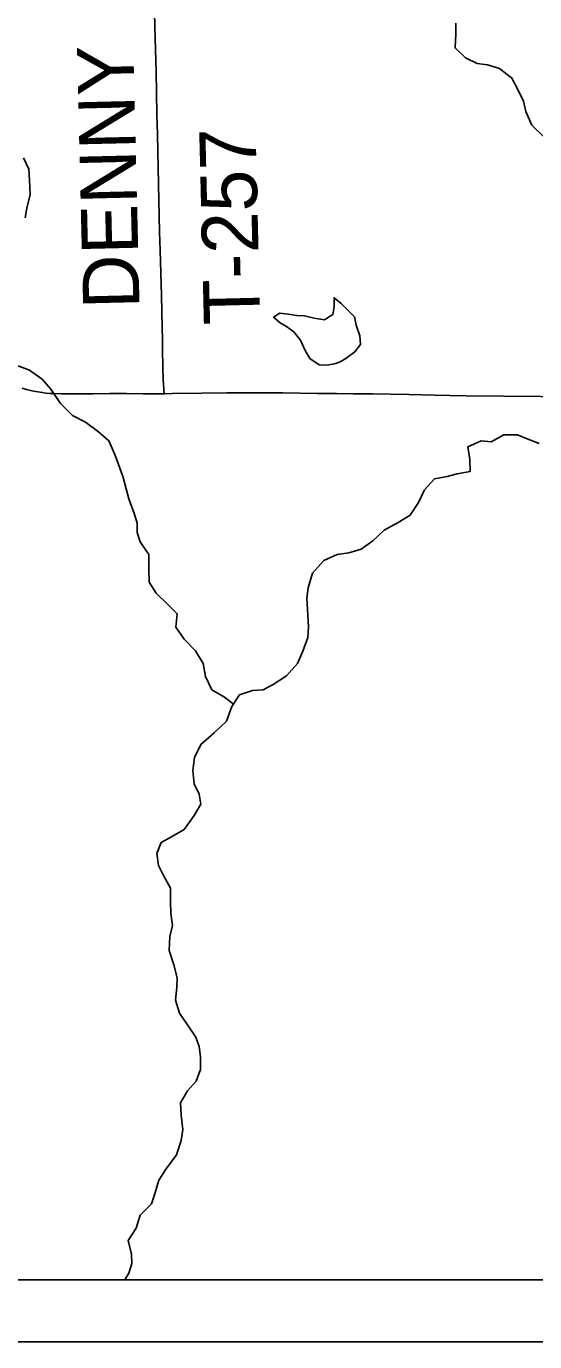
# Model space of a CAD drawing. Extents: x 0 to 34, y 0 to 22.
# Drawn here: x 4.698 to 5.21, y 13.563 to 14.889 of the extents above; entities that cross this region are included whole.
import ezdxf

# ---------------------------------------------------------------- set-up
doc = ezdxf.new("R2010")
doc.units = 0
for name, color, linetype in [('Default', 7, 'Continuous'), ('GM_X_Minor_Lake', 7, 'Continuous'), ('GM_X_Minor_River', 7, 'Continuous'), ('GM_X_Township_Road', 7, 'Continuous'), ('GM_X_Township_Road_Text', 7, 'Continuous'), ('SH_Cut_Line', 7, 'Continuous'), ('SH_Data', 7, 'Continuous')]:
    doc.layers.add(name, color=color, linetype=linetype)

msp = doc.modelspace()

# ---------------------------------------------------------------- linework, layer by layer
at = {"layer": 'Default'}
msp.add_lwpolyline([(2.9696, 13.6252), (8.4279, 13.6252), (8.4024, 15.1386), (8.4023, 15.1576), (8.3761, 15.1587), (8.1234, 15.1688), (7.9465, 15.1727), (5.5157, 15.319), (4.819, 15.349), (4.2393, 15.3805), (4.2078, 15.3826), (3.1796, 15.4266), (3.1343, 15.4291), (3.0617, 14.6751), (3.0457, 14.4958), (3.0429, 14.4692)], close=True, dxfattribs=at)
at = {"layer": 'GM_X_Minor_Lake'}
for points in [[(5.0139, 14.5506), (5.0196, 14.5539), (5.0285, 14.5605), (5.0343, 14.568), (5.0334, 14.5768), (5.0298, 14.5875), (5.0281, 14.5958), (5.0221, 14.602), (5.0147, 14.6094), (5.0076, 14.6152), (5.0078, 14.6061), (5.0062, 14.5982), (5.0001, 14.5943)], [(5.0001, 14.5943), (4.9981, 14.593), (4.9875, 14.5947), (4.9777, 14.5968), (4.9701, 14.5974), (4.9615, 14.5987), (4.9528, 14.5996), (4.9466, 14.5956), (4.9533, 14.5897), (4.9597, 14.5862), (4.9671, 14.5807), (4.9738, 14.5723), (4.9781, 14.5627), (4.9833, 14.5539), (4.9926, 14.5476), (5.0006, 14.5471), (5.0093, 14.5488), (5.0139, 14.5506)]]:
    msp.add_lwpolyline(points, dxfattribs=at)
at = {"layer": 'GM_X_Minor_River'}
for points in [[(5.2197, 14.7768), (5.2067, 14.7892), (5.2009, 14.803), (5.1985, 14.8133), (5.1927, 14.8251), (5.1868, 14.8366), (5.1741, 14.8464), (5.1621, 14.85), (5.1519, 14.8514), (5.1399, 14.8569), (5.1295, 14.867), (5.1302, 14.881), (5.1304, 14.892)], [(4.6963, 14.6958), (4.6981, 14.7056), (4.7014, 14.7192), (4.7009, 14.7336), (4.7, 14.7446), (4.6949, 14.7561)], [(4.9062, 14.2055), (4.8971, 14.2126), (4.8844, 14.22), (4.8782, 14.2334), (4.8758, 14.2464), (4.8681, 14.2591), (4.8566, 14.2711), (4.8482, 14.283), (4.8496, 14.2966), (4.8399, 14.3063), (4.8284, 14.3175), (4.8214, 14.3283), (4.821, 14.3423), (4.8209, 14.3564), (4.8124, 14.3691), (4.8092, 14.3786), (4.8094, 14.3881), (4.8062, 14.3976), (4.8008, 14.4125), (4.798, 14.4225), (4.7952, 14.4339), (4.7916, 14.4442), (4.7869, 14.4572), (4.7808, 14.471), (4.7703, 14.4799), (4.7573, 14.4897), (4.7442, 14.4964), (4.7319, 14.5084), (4.7224, 14.523), (4.7135, 14.533), (4.7008, 14.542), (4.6872, 14.5472)], [(4.7969, 13.6252), (4.8008, 13.6317), (4.804, 13.6415), (4.8034, 13.651), (4.8003, 13.6647), (4.8081, 13.6771), (4.8122, 13.6903), (4.8238, 13.7018), (4.827, 13.712), (4.8311, 13.7256), (4.8385, 13.7372), (4.849, 13.751), (4.8535, 13.7657), (4.8552, 13.7767), (4.8537, 13.7911), (4.8528, 13.8037), (4.8598, 13.8157), (4.8687, 13.8254), (4.8732, 13.837), (4.873, 13.8499), (4.8717, 13.8602), (4.8685, 13.8698), (4.8601, 13.8821), (4.852, 13.894), (4.8477, 13.907), (4.8491, 13.9202), (4.8497, 13.9297), (4.8461, 13.9427), (4.8415, 13.9572), (4.8422, 13.9712), (4.8447, 13.9822), (4.843, 13.9944), (4.8429, 14.0069), (4.8428, 14.0198), (4.8358, 14.0328), (4.8307, 14.0428), (4.8291, 14.055), (4.8335, 14.0659), (4.8431, 14.0714), (4.8565, 14.0791), (4.8666, 14.0933), (4.8733, 14.1045), (4.8716, 14.1148), (4.8665, 14.1252), (4.8653, 14.1385), (4.8671, 14.1517), (4.8734, 14.1649), (4.8869, 14.1767), (4.8993, 14.1883), (4.9045, 14.203), (4.9123, 14.2149), (4.9253, 14.2192), (4.9363, 14.2198), (4.9462, 14.2253), (4.9597, 14.2341), (4.9709, 14.2464), (4.9761, 14.2588), (4.9813, 14.2728), (4.9819, 14.2834), (4.9802, 14.3122), (4.9816, 14.3228), (4.986, 14.3375), (4.9973, 14.3502), (5.0107, 14.3564), (5.0225, 14.3581), (5.035, 14.3616), (5.0466, 14.3701), (5.0582, 14.3809), (5.072, 14.3886), (5.0842, 14.3959), (5.0928, 14.4087), (5.0988, 14.4214), (5.1088, 14.4326), (5.1214, 14.435), (5.1317, 14.4375), (5.1446, 14.4399), (5.1445, 14.452), (5.1425, 14.465), (5.1559, 14.4708), (5.1657, 14.4698), (5.1787, 14.4768), (5.1924, 14.4769), (5.2021, 14.4729), (5.2141, 14.4681)]]:
    msp.add_lwpolyline(points, dxfattribs=at)
at = {"layer": 'GM_X_Township_Road'}
for points in [[(4.8363, 14.5184), (4.8356, 14.5326), (4.8352, 14.5452), (4.8349, 14.563), (4.8347, 14.5727), (4.8344, 14.5856), (4.8336, 14.6173), (4.8324, 14.6629), (4.8319, 14.6816), (4.8312, 14.7132), (4.8296, 14.7797), (4.8292, 14.8002), (4.8283, 14.8431), (4.8269, 14.8878), (4.8259, 14.9357), (4.8251, 14.9717), (4.8242, 15.0154), (4.8227, 15.0828), (4.8213, 15.2078), (4.8208, 15.2684), (4.8201, 15.3196), (4.8193, 15.3485)], [(4.6933, 14.524), (4.6976, 14.5228), (4.7032, 14.5214), (4.7093, 14.5202), (4.7139, 14.5195), (4.717, 14.5191), (4.7213, 14.5187), (4.7252, 14.5186), (4.7326, 14.5184), (4.7475, 14.5183), (4.7649, 14.5184), (4.7817, 14.5186), (4.7984, 14.5185), (4.8152, 14.5184), (4.8332, 14.5184), (4.8363, 14.5184)], [(4.8363, 14.5184), (4.8444, 14.5185), (4.8739, 14.5189), (4.8996, 14.5193), (4.9254, 14.5194), (4.9561, 14.5193), (4.9908, 14.5187), (5.0099, 14.5185), (5.027, 14.5183), (5.0466, 14.5182), (5.0646, 14.518), (5.0833, 14.5177), (5.1087, 14.5171), (5.1242, 14.5167), (5.1404, 14.5164), (5.254, 14.5151), (5.3062, 14.5144), (5.3596, 14.5137), (5.3923, 14.5133), (5.4439, 14.5126)]]:
    msp.add_lwpolyline(points, dxfattribs=at)
at = {"layer": 'SH_Cut_Line'}
msp.add_lwpolyline([(2.9696, 13.6252), (9.0621, 13.6252), (9.0621, 20.4252), (3.5682, 20.4252), (3.5424, 20.1754), (3.5231, 19.8516), (3.5169, 19.7823), (3.5125, 19.7343), (3.5092, 19.6961), (3.5066, 19.6647), (3.4966, 19.5464), (3.4903, 19.4759), (3.4748, 19.2963), (3.47, 19.2407), (3.2768, 17.1355), (3.2667, 16.919), (3.1974, 16.1596), (3.1343, 15.4291), (3.0617, 14.6751), (3.0457, 14.4958), (3.0429, 14.4692)], close=True, dxfattribs=at)
at = {"layer": 'SH_Data'}
msp.add_line((2.1704, 13.5628), (9.1704, 13.5628), dxfattribs=at)

# ---------------------------------------------------------------- texts
at = {"layer": 'GM_X_Township_Road_Text'}
for s, rotation, p in [('DENNY', 91.373, (4.8117, 14.6045)), ('T-257', 91.3844, (4.9333, 14.5885))]:
    msp.add_text(s, height=0.05682, rotation=rotation, dxfattribs=at).set_placement(p)

doc.saveas('drawing.dxf')
